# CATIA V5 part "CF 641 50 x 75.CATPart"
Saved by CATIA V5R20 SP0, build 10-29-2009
Part number: CF 641 50 x 75
Definition: NONE
Nomenclature: CF 641 50 x 75
Source: Unknown
Description: CF 641 50 x 75
Bounding box of the stored display mesh (mm): x -40 to 35, y -39.5 to 39.5, z -39.5 to 39.5
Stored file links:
  C:\Users\Utente\Desktop\IO LAVORO\3D X SITO CF\X SITO\CF 641\CF 641 50 x 75.CATPart
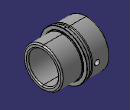
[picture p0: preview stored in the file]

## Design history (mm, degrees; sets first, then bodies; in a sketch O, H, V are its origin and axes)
Body1 "CF 641 50 x 75" (main body)
  Solid1: solid without history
